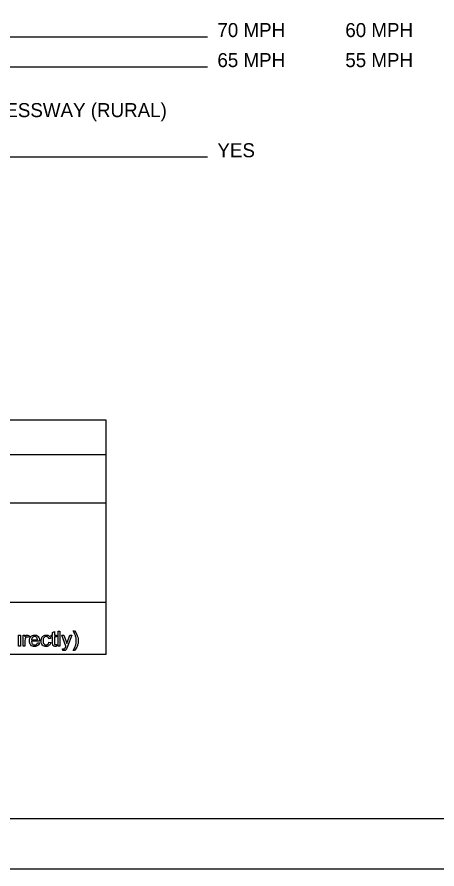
# Model space of a CAD drawing. Extents: x 0 to 64.8, y -5 to 22.
# Drawn here: x 5.74 to 9.93, y 0 to 8.51 of the extents above; entities that cross this region are included whole.
import ezdxf

# ---------------------------------------------------------------- set-up
doc = ezdxf.new("R2010")
doc.units = 0
for name, color, linetype in [('SH_Border', 7, 'Continuous'), ('SH_Cut_Line', 7, 'Continuous'), ('SH_Data', 7, 'Continuous'), ('SH_Text', 7, 'Continuous')]:
    doc.layers.add(name, color=color, linetype=linetype)

msp = doc.modelspace()

# ---------------------------------------------------------------- linework, layer by layer
at = {"layer": 'SH_Border'}
msp.add_lwpolyline([(1.5, 21.5), (33.5, 21.5), (33.5, 0.5), (1.5, 0.5)], close=True, dxfattribs=at)
at = {"layer": 'SH_Cut_Line'}
msp.add_lwpolyline([(0, 0), (34, 0), (34, 22), (0, 22)], close=True, dxfattribs=at)
at = {"layer": 'SH_Data'}
for p, q in [((7.6368, 8.3062), (3.6035, 8.3062)), ((7.6368, 8.0062), (3.4488, 8.0062)), ((7.6368, 7.1062), (3.5243, 7.1062)), ((6.6275, 4.4803), (2.3775, 4.4803)), ((6.6275, 2.1428), (6.6275, 4.4803)), ((2.3775, 4.1387), (6.6275, 4.1387)), ((2.3775, 3.6553), (6.6275, 3.6553)), ((6.6275, 2.6607), (2.3775, 2.6607)), ((6.6275, 2.1428), (2.3775, 2.1428))]:
    msp.add_line(p, q, dxfattribs=at)
at = {"layer": 'SH_Text'}
for points in [[(5.7509, 2.2239), (5.7509, 2.3328), (5.7693, 2.3328), (5.7693, 2.2239), (5.7509, 2.2239)], [(5.7971, 2.2239), (5.7971, 2.3328), (5.8137, 2.3328), (5.8137, 2.3163)], [(5.8562, 2.3293), (5.8497, 2.3122)], [(6.0712, 2.3007), (6.0532, 2.298)], [(6.092, 2.2558), (6.092, 2.3185), (6.0784, 2.3185), (6.0784, 2.3328), (6.092, 2.3328), (6.092, 2.3597), (6.1105, 2.3708), (6.1105, 2.3328), (6.1289, 2.3328), (6.1289, 2.3185), (6.1105, 2.3185), (6.1105, 2.2547)], [(6.1465, 2.2239), (6.1465, 2.3741), (6.1649, 2.3741), (6.1649, 2.2239), (6.1465, 2.2239)], [(6.2243, 2.2238), (6.183, 2.3328), (6.2029, 2.3328), (6.2255, 2.2699)], [(6.241, 2.2693), (6.2643, 2.3328), (6.2827, 2.3328), (6.2414, 2.222)], [(6.2974, 2.3766), (6.3105, 2.3766)], [(5.8155, 2.2809), (5.8155, 2.2239), (5.7971, 2.2239)], [(5.9611, 2.2736), (5.88, 2.2736)], [(5.881, 2.2887), (5.9418, 2.2887)], [(5.9416, 2.2591), (5.9606, 2.2567)], [(6.0548, 2.2638), (6.0729, 2.2613)], [(6.1289, 2.2404), (6.1315, 2.2241)], [(6.1928, 2.1821), (6.1907, 2.1995)], [(6.3105, 2.1798), (6.2974, 2.1798)]]:
    msp.add_lwpolyline(points, dxfattribs=at)
for points in [[(5.8137, 2.3163), (5.8201, 2.3278), (5.8254, 2.3315), (5.8308, 2.3352), (5.8372, 2.3352), (5.8466, 2.3352), (5.8562, 2.3293)], [(5.8497, 2.3122), (5.843, 2.3162), (5.8363, 2.3162), (5.8302, 2.3162), (5.8255, 2.3125), (5.8207, 2.3089), (5.8186, 2.3024), (5.8155, 2.2926), (5.8155, 2.2809)], [(5.9606, 2.2567), (5.9561, 2.24), (5.9439, 2.2307), (5.9317, 2.2215), (5.9128, 2.2215), (5.8889, 2.2215), (5.875, 2.2362), (5.861, 2.2509), (5.861, 2.2774), (5.861, 2.3049), (5.8751, 2.32), (5.8892, 2.3352), (5.9118, 2.3352), (5.9336, 2.3352), (5.9474, 2.3203), (5.9612, 2.3055), (5.9612, 2.2785), (5.9612, 2.2769), (5.9611, 2.2736)], [(5.9418, 2.2887), (5.9405, 2.3025), (5.9348, 2.3094), (5.926, 2.3201), (5.912, 2.3201), (5.8993, 2.3201), (5.8906, 2.3115), (5.8819, 2.303), (5.881, 2.2887)], [(6.0729, 2.2613), (6.07, 2.2427), (6.0577, 2.2321), (6.0455, 2.2215), (6.0277, 2.2215), (6.0053, 2.2215), (5.9917, 2.2361), (5.9782, 2.2507), (5.9782, 2.2779), (5.9782, 2.2955), (5.984, 2.3088), (5.9899, 2.322), (6.0018, 2.3286), (6.0137, 2.3352), (6.0278, 2.3352), (6.0455, 2.3352), (6.0568, 2.3262), (6.068, 2.3172), (6.0712, 2.3007)], [(6.0532, 2.298), (6.0507, 2.309), (6.0442, 2.3145), (6.0377, 2.3201), (6.0285, 2.3201), (6.0146, 2.3201), (6.0059, 2.3101), (5.9972, 2.3001), (5.9972, 2.2784), (5.9972, 2.2565), (6.0056, 2.2466), (6.014, 2.2366), (6.0275, 2.2366), (6.0384, 2.2366), (6.0456, 2.2433), (6.0529, 2.2499), (6.0548, 2.2638)], [(6.2974, 2.1798), (6.3279, 2.2289), (6.3279, 2.2782), (6.3279, 2.2974), (6.3235, 2.3164), (6.32, 2.3317), (6.3138, 2.3459), (6.3098, 2.3551), (6.2974, 2.3766)], [(6.3105, 2.3766), (6.3298, 2.3509), (6.339, 2.325), (6.3469, 2.3026), (6.3469, 2.2783), (6.3469, 2.2506), (6.3363, 2.2248), (6.3257, 2.199), (6.3105, 2.1798)], [(5.88, 2.2736), (5.881, 2.2557), (5.8901, 2.2462), (5.8992, 2.2366), (5.9129, 2.2366), (5.923, 2.2366), (5.9302, 2.242), (5.9374, 2.2473), (5.9416, 2.2591)], [(6.1315, 2.2241), (6.1238, 2.2224), (6.1176, 2.2224), (6.1076, 2.2224), (6.1021, 2.2256), (6.0965, 2.2288), (6.0943, 2.234), (6.092, 2.2392), (6.092, 2.2558)], [(6.1105, 2.2547), (6.1105, 2.2468), (6.1114, 2.2445), (6.1124, 2.2423), (6.1146, 2.2409), (6.1168, 2.2396), (6.1209, 2.2396), (6.1239, 2.2396), (6.1289, 2.2404)], [(6.1907, 2.1995), (6.1967, 2.1978), (6.2012, 2.1978), (6.2074, 2.1978), (6.211, 2.1999), (6.2147, 2.2019), (6.2171, 2.2056), (6.2188, 2.2084), (6.2227, 2.2193), (6.2232, 2.2209), (6.2243, 2.2238)], [(6.2414, 2.222), (6.2348, 2.2042), (6.2311, 2.1974), (6.2262, 2.1883), (6.2198, 2.1841), (6.2135, 2.1799), (6.2046, 2.1799), (6.1993, 2.1799), (6.1928, 2.1821)], [(6.2255, 2.2699), (6.2299, 2.258), (6.2334, 2.2448), (6.2366, 2.2572), (6.241, 2.2693)]]:
    msp.add_open_spline(points, degree=3, dxfattribs=at)

# ---------------------------------------------------------------- texts
for s, p in [('70 MPH', (7.7368, 8.3062)), ('60 MPH', (9.0139, 8.3062)), ('65 MPH', (7.7368, 8.0062)), ('55 MPH', (9.0139, 8.0062)), ('US 24: 02 OTHER FREEWAY AND EXPRESSWAY (RURAL)', (2.0928, 7.5067)), ('YES', (7.7368, 7.1062))]:
    msp.add_text(s, height=0.14, dxfattribs=at).set_placement(p)

doc.saveas('drawing.dxf')
